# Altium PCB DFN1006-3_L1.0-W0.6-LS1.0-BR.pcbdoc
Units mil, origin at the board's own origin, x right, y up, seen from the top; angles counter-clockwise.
Board outline 560 x 540 mil, 2 copper layers (Top Layer, Bottom Layer), stack 0 mil thick; 1 components, 0 nets, 3 pads, 0 vias.
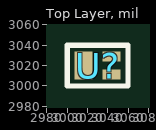
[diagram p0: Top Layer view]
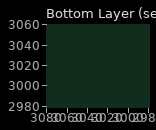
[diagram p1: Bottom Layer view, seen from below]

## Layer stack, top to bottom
Top Layer: signal copper (thickness not stored)
Bottom Layer: signal copper (thickness not stored)

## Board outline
3310,2750 2750,2750 2750,3290 3310,3290

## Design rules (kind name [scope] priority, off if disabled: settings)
PasteMaskExpansion "Paste Mask Expansion" [All] p1: expansion=0
SolderMaskExpansion "Solder Mask Expansion" [IsVia] p1: expansion=-1000 istentingtop=TRUE
SolderMaskExpansion "Solder Mask Expansion" [All] p2: expansion=2 istentingtop=FALSE

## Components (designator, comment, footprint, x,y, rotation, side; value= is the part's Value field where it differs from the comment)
U? "" DFN1006-3_L1.0-W0.6-LS1.0-BR 3030,3020 r0 top

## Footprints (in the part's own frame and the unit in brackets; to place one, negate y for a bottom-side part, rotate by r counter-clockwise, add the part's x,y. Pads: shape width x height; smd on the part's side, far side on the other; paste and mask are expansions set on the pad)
DFN1006-3_L1.0-W0.6-LS1.0-BR [mm]
  rect 0.45x0.25 smd: 1(0.35,-0.225) 3(0.35,0.225)
  rect 0.45x0.7 smd: 2(-0.35,0)
  silkscreen extent -0.76,-0.51 0.76,0.51

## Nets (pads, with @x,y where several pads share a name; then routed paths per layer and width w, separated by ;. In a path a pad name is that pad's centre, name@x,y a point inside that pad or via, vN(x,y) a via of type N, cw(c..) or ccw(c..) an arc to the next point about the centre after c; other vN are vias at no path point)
pads on no net: U?.1 U?.2 U?.3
